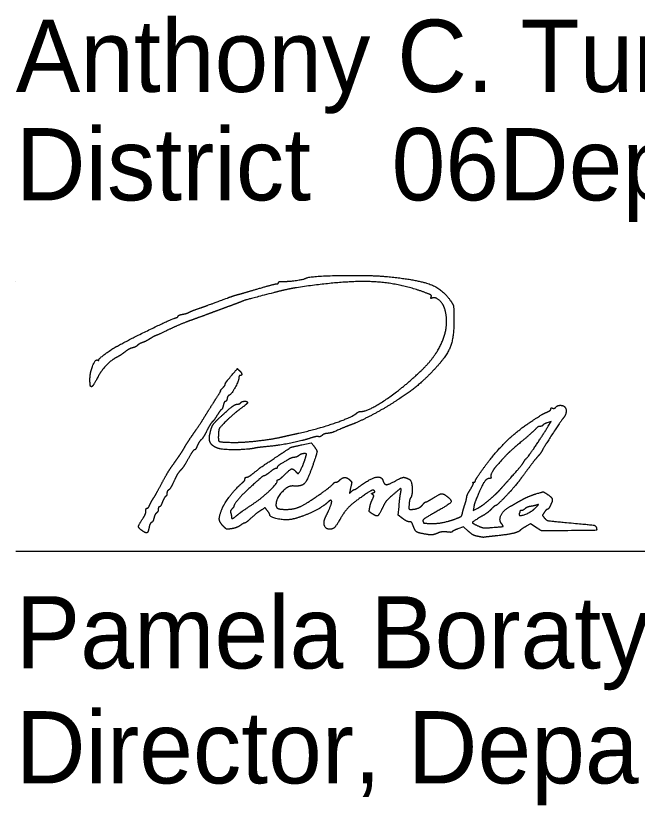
# Model space of a CAD drawing. Extents: x 0 to 34, y 0 to 22.
# Drawn here: x 24.528 to 25.732, y 7.305 to 8.834 of the extents above; entities that cross this region are included whole.
import ezdxf

# ---------------------------------------------------------------- set-up
doc = ezdxf.new("R2010")
doc.units = 0
doc.layers.add('GM_X_Minor_Lake', color=7, linetype='Continuous')
doc.layers.add('GM_X_Minor_Lake_Text', color=7, linetype='Continuous')

msp = doc.modelspace()

# ---------------------------------------------------------------- linework, layer by layer
at = {"layer": 'GM_X_Minor_Lake'}
for points in [[(25.5597, 8.039), (25.5651, 8.0479), (25.5577, 8.0453)], [(25.0824, 8.0028), (25.1004, 8.0068), (25.1051, 8.0007)], [(25.2773, 7.86), (25.269, 7.8663), (25.2704, 7.8834)], [(25.4153, 7.882), (25.4143, 7.8755), (25.4229, 7.8799)], [(25.5361, 7.8426), (25.5255, 7.8494), (25.5171, 7.8449)], [(25.4043, 7.8356), (25.3951, 7.8439), (25.3845, 7.8398)]]:
    msp.add_lwpolyline(points, dxfattribs=at)
for points in [[(25.0368, 8.3169), (25.0368, 8.3183), (25.0408, 8.3193), (25.0458, 8.3192)], [(25.0458, 8.3192), (25.0554, 8.3189), (25.0864, 8.3232), (25.0898, 8.3254)], [(25.3205, 8.2977), (25.2699, 8.3167), (25.1619, 8.3207), (25.0716, 8.3069)], [(25.0898, 8.3254), (25.0966, 8.3295), (25.2136, 8.3318), (25.248, 8.3285)], [(25.248, 8.3285), (25.3072, 8.3226), (25.3548, 8.3043), (25.3706, 8.2813)], [(24.9612, 8.2946), (24.9665, 8.296), (24.9839, 8.301), (25, 8.3058)], [(25, 8.3058), (25.0161, 8.3105), (25.031, 8.3144), (25.033, 8.3144)], [(25.0716, 8.3069), (25.0623, 8.3055), (25.0424, 8.3011), (25.0272, 8.2972)], [(25.033, 8.3144), (25.0351, 8.3144), (25.0368, 8.3156), (25.0368, 8.3169)], [(24.9372, 8.2868), (24.9451, 8.2897), (24.9559, 8.2933), (24.9612, 8.2946)], [(25.0272, 8.2972), (24.9762, 8.284), (24.9719, 8.2828), (24.9612, 8.2784)], [(25.3328, 8.2891), (25.3338, 8.2916), (25.3303, 8.294), (25.3205, 8.2977)], [(25.3352, 8.287), (25.3326, 8.286), (25.3319, 8.2866), (25.3328, 8.2891)], [(24.8808, 8.2662), (24.8955, 8.2713), (24.9019, 8.2737), (24.9372, 8.2868)], [(24.9612, 8.2784), (24.9585, 8.2774), (24.9483, 8.2735), (24.9384, 8.27)], [(25.3586, 8.2671), (25.3553, 8.2769), (25.3409, 8.2892), (25.3352, 8.287)], [(25.3706, 8.2813), (25.3755, 8.274), (25.3764, 8.2697), (25.3768, 8.2518)], [(24.8514, 8.2556), (24.8563, 8.2565), (24.8615, 8.2581), (24.8628, 8.259)], [(24.8628, 8.259), (24.8641, 8.26), (24.8722, 8.2632), (24.8808, 8.2662)], [(24.9048, 8.2575), (24.8962, 8.2543), (24.88, 8.2484), (24.8688, 8.2444)], [(24.9384, 8.27), (24.9285, 8.2664), (24.9134, 8.2608), (24.9048, 8.2575)], [(25.3131, 8.1459), (25.344, 8.1753), (25.3679, 8.2389), (25.3586, 8.2671)], [(24.7248, 8.194), (24.755, 8.2103), (24.8286, 8.2459), (24.837, 8.2484)], [(24.8688, 8.2444), (24.8576, 8.2404), (24.8372, 8.2319), (24.8236, 8.2254)], [(24.837, 8.2484), (24.84, 8.2492), (24.8424, 8.2508), (24.8424, 8.2519)], [(24.8424, 8.2519), (24.8424, 8.253), (24.8464, 8.2547), (24.8514, 8.2556)], [(25.3768, 8.2518), (25.3775, 8.2111), (25.3614, 8.1714), (25.332, 8.1415)], [(24.7977, 8.2136), (24.7971, 8.2136), (24.7927, 8.2111), (24.7877, 8.208)], [(24.8236, 8.2254), (24.8099, 8.2189), (24.7983, 8.2136), (24.7977, 8.2136)], [(24.7729, 8.2005), (24.7697, 8.1994), (24.7655, 8.1971), (24.7637, 8.1953)], [(24.7877, 8.208), (24.7828, 8.2049), (24.7761, 8.2015), (24.7729, 8.2005)], [(24.6888, 8.1674), (24.6888, 8.1696), (24.7142, 8.1883), (24.7248, 8.194)], [(24.7392, 8.1824), (24.7346, 8.1788), (24.7274, 8.1742), (24.7233, 8.1721)], [(24.754, 8.1905), (24.7505, 8.1896), (24.7438, 8.186), (24.7392, 8.1824)], [(24.7637, 8.1953), (24.7619, 8.1935), (24.7576, 8.1913), (24.754, 8.1905)], [(24.6716, 8.1295), (24.6717, 8.1427), (24.6823, 8.1693), (24.6865, 8.1668)], [(24.6865, 8.1668), (24.6877, 8.166), (24.6888, 8.1663), (24.6888, 8.1674)], [(24.7233, 8.1721), (24.7129, 8.1667), (24.693, 8.1459), (24.6868, 8.1338)], [(24.939, 8.1285), (24.9575, 8.1506), (24.9568, 8.15), (24.9609, 8.1467)], [(24.9624, 8.1368), (24.9611, 8.1368), (24.96, 8.1345), (24.96, 8.1317)], [(24.9609, 8.1467), (24.9652, 8.1431), (24.9661, 8.1368), (24.9624, 8.1368)], [(25.1964, 8.0672), (25.2105, 8.0672), (25.2786, 8.1131), (25.3131, 8.1459)], [(25.332, 8.1415), (25.3134, 8.1226), (25.281, 8.0977), (25.2505, 8.0788)], [(24.673, 8.1158), (24.6722, 8.1166), (24.6716, 8.1228), (24.6716, 8.1295)], [(24.6868, 8.1338), (24.6801, 8.1209), (24.6748, 8.114), (24.673, 8.1158)], [(24.9288, 8.1128), (24.9314, 8.1155), (24.9336, 8.1186), (24.9336, 8.1198)], [(24.9336, 8.1198), (24.9336, 8.121), (24.936, 8.1249), (24.939, 8.1285)], [(24.96, 8.1317), (24.96, 8.1262), (24.9441, 8.0984), (24.9409, 8.0984)], [(24.916, 8.0924), (24.9216, 8.101), (24.9256, 8.108), (24.925, 8.108)], [(24.925, 8.108), (24.9245, 8.108), (24.9261, 8.1102), (24.9288, 8.1128)], [(24.894, 8.0574), (24.9006, 8.068), (24.9105, 8.0838), (24.916, 8.0924)], [(24.9374, 8.0924), (24.9366, 8.0891), (24.9349, 8.0864), (24.9337, 8.0864)], [(24.9409, 8.0984), (24.9398, 8.0984), (24.9382, 8.0957), (24.9374, 8.0924)], [(24.9252, 8.0575), (24.9409, 8.0721), (24.9536, 8.0816), (24.9576, 8.0816)], [(24.93, 8.0793), (24.9291, 8.0753), (24.9274, 8.0714), (24.9261, 8.0707)], [(24.9337, 8.0864), (24.9325, 8.0864), (24.9309, 8.0832), (24.93, 8.0793)], [(24.9576, 8.0816), (24.9601, 8.0816), (24.9628, 8.0827), (24.9636, 8.084)], [(24.9768, 8.0844), (24.9768, 8.0833), (24.97, 8.0774), (24.9618, 8.0713)], [(24.9636, 8.084), (24.9654, 8.0869), (24.9768, 8.0873), (24.9768, 8.0844)], [(25.2505, 8.0788), (25.2313, 8.067), (25.1901, 8.046), (25.176, 8.0409)], [(25.5648, 8.0722), (25.5648, 8.0737), (25.5663, 8.0744), (25.5682, 8.0736)], [(25.5682, 8.0736), (25.5701, 8.0729), (25.5729, 8.0739), (25.5745, 8.0758)], [(25.5745, 8.0758), (25.5761, 8.0777), (25.5798, 8.0792), (25.5827, 8.0792)], [(25.5827, 8.0792), (25.5921, 8.0792), (25.5959, 8.0632), (25.5885, 8.0542)], [(24.9176, 8.0592), (24.9142, 8.0537), (24.9101, 8.0481), (24.9084, 8.0468)], [(24.9261, 8.0707), (24.9248, 8.0699), (24.921, 8.0647), (24.9176, 8.0592)], [(24.9618, 8.0713), (24.9535, 8.0652), (24.941, 8.0543), (24.934, 8.0471)], [(25.0764, 8.0253), (25.1133, 8.0335), (25.1796, 8.0564), (25.1882, 8.0639)], [(25.1882, 8.0639), (25.1903, 8.0657), (25.1939, 8.0672), (25.1964, 8.0672)], [(25.528, 8.0488), (25.5469, 8.0611), (25.5488, 8.0622), (25.557, 8.0659)], [(25.557, 8.0659), (25.5613, 8.0678), (25.5648, 8.0706), (25.5648, 8.0722)], [(24.8722, 8.0244), (24.8776, 8.0319), (24.8874, 8.0467), (24.894, 8.0574)], [(24.9084, 8.0468), (24.9068, 8.0455), (24.9021, 8.0378), (24.8981, 8.0299)], [(24.9038, 8.0228), (24.9066, 8.0359), (24.9127, 8.0459), (24.9252, 8.0575)], [(24.934, 8.0471), (24.9233, 8.0362), (24.9211, 8.0325), (24.9206, 8.0243)], [(25.4334, 7.9563), (25.4556, 7.9871), (25.5007, 8.0312), (25.528, 8.0488)], [(25.5885, 8.0542), (25.5843, 8.0492), (25.5515, 7.9987), (25.5483, 7.9926)], [(25.5577, 8.0453), (25.5537, 8.0439), (25.5498, 8.0418), (25.549, 8.0406)], [(24.8981, 8.0299), (24.8941, 8.0219), (24.889, 8.0139), (24.8868, 8.0121)], [(25.1603, 8.0347), (25.1433, 8.0272), (25.1384, 8.0256), (25.1318, 8.0248)], [(25.176, 8.0409), (25.1714, 8.0392), (25.1643, 8.0364), (25.1603, 8.0347)], [(25.5349, 8.033), (25.5322, 8.0301), (25.5197, 8.019), (25.5072, 8.0084)], [(25.5169, 7.976), (25.5197, 7.978), (25.5479, 8.0195), (25.5597, 8.039)], [(25.5437, 8.0384), (25.5415, 8.0384), (25.5375, 8.036), (25.5349, 8.033)], [(25.549, 8.0406), (25.5483, 8.0394), (25.5459, 8.0384), (25.5437, 8.0384)], [(24.8555, 7.9988), (24.8593, 8.0054), (24.8669, 8.0169), (24.8722, 8.0244)], [(24.9192, 7.996), (24.9087, 7.9999), (24.9016, 8.0123), (24.9038, 8.0228)], [(24.9206, 8.0243), (24.9197, 8.0108), (24.9238, 8.008), (24.9444, 8.0074)], [(24.9444, 8.0074), (24.9636, 8.0069), (25.0215, 8.013), (25.0428, 8.0178)], [(25.0962, 8.0148), (25.0797, 8.0095), (25.0346, 8.001), (25.0108, 7.9988)], [(25.0428, 8.0178), (25.0507, 8.0196), (25.0658, 8.023), (25.0764, 8.0253)], [(25.1142, 8.0185), (25.1125, 8.0191), (25.1044, 8.0175), (25.0962, 8.0148)], [(25.121, 8.0207), (25.1189, 8.0189), (25.1158, 8.0179), (25.1142, 8.0185)], [(25.1318, 8.0248), (25.1279, 8.0244), (25.123, 8.0225), (25.121, 8.0207)], [(24.8425, 7.9782), (24.8458, 7.9829), (24.8517, 7.9922), (24.8555, 7.9988)], [(24.8796, 8.0008), (24.8777, 7.9964), (24.8752, 7.9928), (24.8739, 7.9928)], [(24.8868, 8.0121), (24.8847, 8.0103), (24.8814, 8.0052), (24.8796, 8.0008)], [(25.0108, 7.9988), (25.0025, 7.998), (24.9933, 7.9968), (24.9904, 7.9961)], [(25.0284, 7.9764), (25.06, 7.9974), (25.0614, 7.9981), (25.0824, 8.0028)], [(25.1051, 8.0007), (25.1117, 7.9919), (25.1115, 7.987), (25.1038, 7.9645)], [(25.5072, 8.0084), (25.4876, 7.9919), (25.4759, 7.9805), (25.4592, 7.9617)], [(24.8739, 7.9928), (24.8726, 7.9928), (24.8672, 7.9849), (24.8618, 7.9753)], [(24.9904, 7.9961), (24.9767, 7.9931), (24.9272, 7.993), (24.9192, 7.996)], [(25.0765, 7.982), (25.074, 7.98), (25.07, 7.9784), (25.0678, 7.9784)], [(25.0864, 7.9856), (25.0835, 7.9855), (25.0791, 7.9839), (25.0765, 7.982)], [(25.0897, 7.979), (25.0914, 7.9848), (25.091, 7.9856), (25.0864, 7.9856)], [(25.5483, 7.9926), (25.5466, 7.9891), (25.5427, 7.9836), (25.5397, 7.9804)], [(24.8289, 7.959), (24.833, 7.9648), (24.8391, 7.9734), (24.8425, 7.9782)], [(24.8618, 7.9753), (24.8565, 7.9656), (24.8498, 7.9556), (24.847, 7.9531)], [(24.9892, 7.9484), (25.0029, 7.9595), (25.0009, 7.9581), (25.0284, 7.9764)], [(25.0581, 7.9753), (25.0436, 7.9674), (25.0344, 7.961), (25.0344, 7.959)], [(25.0678, 7.9784), (25.0656, 7.9784), (25.0612, 7.977), (25.0581, 7.9753)], [(25.075, 7.9472), (25.0768, 7.9472), (25.0866, 7.9684), (25.0897, 7.979)], [(25.4817, 7.9331), (25.497, 7.9502), (25.5106, 7.9665), (25.513, 7.9709)], [(25.513, 7.9709), (25.5142, 7.9731), (25.5159, 7.9754), (25.5169, 7.976)], [(25.5397, 7.9804), (25.5367, 7.9772), (25.5278, 7.9659), (25.5199, 7.9552)], [(24.81, 7.9268), (24.8163, 7.9387), (24.8248, 7.9532), (24.8289, 7.959)], [(24.847, 7.9531), (24.8441, 7.9505), (24.8386, 7.9414), (24.8347, 7.9328)], [(25.0317, 7.9568), (25.0303, 7.9568), (25.025, 7.9536), (25.02, 7.9496)], [(25.0344, 7.959), (25.0344, 7.9578), (25.0332, 7.9568), (25.0317, 7.9568)], [(25.0488, 7.9448), (25.0589, 7.955), (25.0654, 7.9568), (25.0704, 7.9508)], [(25.1038, 7.9645), (25.0935, 7.9346), (25.0815, 7.9215), (25.0656, 7.9229)], [(25.4184, 7.933), (25.4184, 7.9344), (25.4251, 7.9449), (25.4334, 7.9563)], [(25.4592, 7.9617), (25.4533, 7.955), (25.4471, 7.9422), (25.4485, 7.9398)], [(25.5199, 7.9552), (25.512, 7.9446), (25.5043, 7.9344), (25.5029, 7.9325)], [(24.9666, 7.9288), (24.9695, 7.9312), (24.972, 7.9347), (24.972, 7.9366)], [(24.972, 7.9366), (24.972, 7.9385), (24.9735, 7.94), (24.9754, 7.94)], [(25.0088, 7.9424), (25.0069, 7.9424), (24.9985, 7.9351), (24.9732, 7.9119)], [(24.9754, 7.94), (24.9772, 7.94), (24.9834, 7.9438), (24.9892, 7.9484)], [(25.02, 7.9496), (25.015, 7.9457), (25.01, 7.9424), (25.0088, 7.9424)], [(25.0368, 7.9352), (25.0381, 7.9352), (25.0435, 7.9396), (25.0488, 7.9448)], [(25.0704, 7.9508), (25.072, 7.9489), (25.0741, 7.9472), (25.075, 7.9472)], [(25.1555, 7.9343), (25.1605, 7.9393), (25.1705, 7.9393), (25.1754, 7.9344)], [(25.1935, 7.9218), (25.2138, 7.9369), (25.2365, 7.9425), (25.2395, 7.9331)], [(25.2633, 7.9327), (25.2752, 7.9393), (25.2825, 7.9401), (25.2907, 7.9355)], [(25.4462, 7.9376), (25.4399, 7.9376), (25.4304, 7.9225), (25.4183, 7.8932)], [(25.4485, 7.9398), (25.4493, 7.9386), (25.4482, 7.9376), (25.4462, 7.9376)], [(24.7946, 7.8992), (24.7968, 7.9025), (24.8037, 7.915), (24.81, 7.9268)], [(24.8347, 7.9328), (24.8307, 7.9243), (24.826, 7.9164), (24.8242, 7.9153)], [(24.9285, 7.8806), (24.933, 7.891), (24.9562, 7.9205), (24.9666, 7.9288)], [(24.9883, 7.8886), (25.0039, 7.899), (25.0344, 7.9278), (25.0344, 7.9321)], [(25.0656, 7.9229), (25.0552, 7.9238), (25.032, 7.8984), (25.032, 7.8861)], [(25.0344, 7.9321), (25.0344, 7.9338), (25.0355, 7.9352), (25.0368, 7.9352)], [(25.1004, 7.8956), (25.119, 7.9079), (25.1414, 7.9246), (25.1431, 7.9274)], [(25.1431, 7.9274), (25.1442, 7.9291), (25.1465, 7.9304), (25.1483, 7.9304)], [(25.1483, 7.9304), (25.1501, 7.9304), (25.1534, 7.9322), (25.1555, 7.9343)], [(25.1754, 7.9344), (25.1786, 7.9312), (25.1788, 7.9288), (25.1767, 7.9196)], [(25.1841, 7.916), (25.1851, 7.916), (25.1893, 7.9186), (25.1935, 7.9218)], [(25.2395, 7.9331), (25.2419, 7.9255), (25.25, 7.9254), (25.2633, 7.9327)], [(25.2907, 7.9355), (25.2951, 7.933), (25.2967, 7.905), (25.2928, 7.8998)], [(25.4086, 7.9161), (25.4125, 7.9224), (25.415, 7.9282), (25.4142, 7.929)], [(25.4142, 7.929), (25.4134, 7.9298), (25.414, 7.9304), (25.4156, 7.9304)], [(25.4156, 7.9304), (25.4171, 7.9304), (25.4184, 7.9316), (25.4184, 7.933)], [(25.4661, 7.9156), (25.4692, 7.9191), (25.4762, 7.927), (25.4817, 7.9331)], [(25.5029, 7.9325), (25.4896, 7.9161), (25.485, 7.911), (25.4732, 7.8988)], [(24.8208, 7.9089), (24.8208, 7.9064), (24.8197, 7.9036), (24.8183, 7.9028)], [(24.8242, 7.9153), (24.8223, 7.9143), (24.8208, 7.9113), (24.8208, 7.9089)], [(24.9732, 7.9119), (24.9641, 7.9035), (24.9504, 7.8865), (24.9504, 7.8835)], [(25.1767, 7.9196), (25.1744, 7.9094), (25.1745, 7.9089), (25.1783, 7.9123)], [(25.1783, 7.9123), (25.1805, 7.9144), (25.1832, 7.916), (25.1841, 7.916)], [(25.2222, 7.9139), (25.2204, 7.9158), (25.2145, 7.913), (25.202, 7.9045)], [(25.2194, 7.9063), (25.2172, 7.9077), (25.2175, 7.9086), (25.2206, 7.9098)], [(25.2187, 7.8965), (25.2215, 7.9027), (25.2217, 7.9049), (25.2194, 7.9063)], [(25.2206, 7.9098), (25.2236, 7.9109), (25.224, 7.9121), (25.2222, 7.9139)], [(25.2633, 7.9099), (25.2474, 7.8958), (25.2437, 7.8914), (25.2382, 7.8801)], [(25.2734, 7.9082), (25.2752, 7.9177), (25.2726, 7.9181), (25.2633, 7.9099)], [(25.2704, 7.8834), (25.2712, 7.8928), (25.2726, 7.9039), (25.2734, 7.9082)], [(25.336, 7.8992), (25.3489, 7.9075), (25.3565, 7.9083), (25.3642, 7.9022)], [(25.4016, 7.9014), (25.4016, 7.9032), (25.4047, 7.9098), (25.4086, 7.9161)], [(25.446, 7.8968), (25.4539, 7.9036), (25.4629, 7.9121), (25.4661, 7.9156)], [(25.506, 7.8948), (25.5139, 7.8993), (25.5271, 7.905), (25.5353, 7.9075)], [(25.5353, 7.9075), (25.5493, 7.9117), (25.5505, 7.9117), (25.5564, 7.9079)], [(25.5564, 7.9079), (25.566, 7.9016), (25.5684, 7.8942), (25.5638, 7.8852)], [(24.7877, 7.8866), (24.7893, 7.8903), (24.7924, 7.8959), (24.7946, 7.8992)], [(24.812, 7.8918), (24.81, 7.8867), (24.8073, 7.8824), (24.8061, 7.8824)], [(24.8183, 7.9028), (24.8169, 7.9019), (24.8141, 7.897), (24.812, 7.8918)], [(25.0519, 7.8776), (25.065, 7.8776), (25.0841, 7.8847), (25.1004, 7.8956)], [(25.1324, 7.8914), (25.1228, 7.8822), (25.084, 7.8635), (25.0656, 7.859)], [(25.1294, 7.8656), (25.1335, 7.8733), (25.14, 7.8896), (25.14, 7.8923)], [(25.14, 7.8923), (25.14, 7.8954), (25.136, 7.8949), (25.1324, 7.8914)], [(25.202, 7.9045), (25.1823, 7.8911), (25.1651, 7.874), (25.1568, 7.8596)], [(25.2136, 7.8808), (25.2144, 7.885), (25.2166, 7.892), (25.2187, 7.8965)], [(25.2928, 7.8998), (25.2916, 7.8982), (25.2903, 7.8925), (25.2899, 7.8872)], [(25.3168, 7.8872), (25.3187, 7.8898), (25.3212, 7.892), (25.3224, 7.892)], [(25.3224, 7.892), (25.3236, 7.892), (25.3297, 7.8953), (25.336, 7.8992)], [(25.3642, 7.9022), (25.3739, 7.8946), (25.367, 7.8867), (25.3354, 7.8689)], [(25.3981, 7.8872), (25.4, 7.8932), (25.4016, 7.8995), (25.4016, 7.9014)], [(25.4183, 7.8932), (25.4172, 7.8906), (25.4159, 7.8855), (25.4153, 7.882)], [(25.4229, 7.8799), (25.4277, 7.8824), (25.4381, 7.8899), (25.446, 7.8968)], [(25.4732, 7.8988), (25.4657, 7.8911), (25.4586, 7.8848), (25.4576, 7.8848)], [(25.4864, 7.8838), (25.4893, 7.8853), (25.4981, 7.8903), (25.506, 7.8948)], [(24.78, 7.8744), (24.78, 7.8775), (24.7811, 7.88), (24.7824, 7.88)], [(24.7824, 7.88), (24.7838, 7.88), (24.7862, 7.883), (24.7877, 7.8866)], [(24.804, 7.8779), (24.804, 7.8754), (24.8024, 7.8721), (24.8005, 7.8706)], [(24.8061, 7.8824), (24.8049, 7.8824), (24.804, 7.8804), (24.804, 7.8779)], [(24.9302, 7.8448), (24.9225, 7.8524), (24.9219, 7.8653), (24.9285, 7.8806)], [(24.9466, 7.8783), (24.9446, 7.8763), (24.9435, 7.873), (24.9442, 7.8711)], [(24.9504, 7.8835), (24.9504, 7.8827), (24.9487, 7.8804), (24.9466, 7.8783)], [(24.9568, 7.8663), (24.9643, 7.8724), (24.9696, 7.8761), (24.9883, 7.8886)], [(25.0041, 7.8765), (24.9959, 7.8711), (24.9933, 7.8691), (24.9821, 7.859)], [(25.0154, 7.8751), (25.0109, 7.8809), (25.0108, 7.8809), (25.0041, 7.8765)], [(25.0199, 7.8677), (25.0199, 7.8685), (25.0179, 7.8719), (25.0154, 7.8751)], [(25.032, 7.8861), (25.032, 7.881), (25.0398, 7.8776), (25.0519, 7.8776)], [(25.2182, 7.8693), (25.2132, 7.8726), (25.2124, 7.8746), (25.2136, 7.8808)], [(25.2382, 7.8801), (25.2315, 7.8664), (25.2267, 7.8638), (25.2182, 7.8693)], [(25.2899, 7.8872), (25.2894, 7.8796), (25.2901, 7.8776), (25.2932, 7.8776)], [(25.2932, 7.8776), (25.3016, 7.8776), (25.3136, 7.8825), (25.3168, 7.8872)], [(25.3933, 7.8702), (25.394, 7.8736), (25.3961, 7.8813), (25.3981, 7.8872)], [(25.449, 7.8779), (25.4454, 7.874), (25.4373, 7.8679), (25.431, 7.8643)], [(25.4576, 7.8848), (25.4565, 7.8848), (25.4526, 7.8817), (25.449, 7.8779)], [(25.4694, 7.8494), (25.4633, 7.8568), (25.4731, 7.8765), (25.4864, 7.8838)], [(25.5033, 7.8695), (25.5008, 7.863), (25.5263, 7.8719), (25.5348, 7.8805)], [(25.5076, 7.8752), (25.506, 7.8752), (25.5048, 7.8748), (25.5048, 7.8742)], [(25.5144, 7.8788), (25.5122, 7.8769), (25.5091, 7.8752), (25.5076, 7.8752)], [(25.5254, 7.8834), (25.5215, 7.8828), (25.5166, 7.8808), (25.5144, 7.8788)], [(25.5372, 7.8861), (25.5345, 7.8851), (25.5292, 7.8839), (25.5254, 7.8834)], [(25.5348, 7.8805), (25.5403, 7.8861), (25.5408, 7.8875), (25.5372, 7.8861)], [(25.5578, 7.8776), (25.5567, 7.8776), (25.554, 7.875), (25.5519, 7.8718)], [(25.5638, 7.8852), (25.5616, 7.881), (25.5589, 7.8776), (25.5578, 7.8776)], [(24.7725, 7.8364), (24.7655, 7.8413), (24.7659, 7.848), (24.7742, 7.8601)], [(24.7742, 7.8601), (24.7774, 7.8648), (24.78, 7.8712), (24.78, 7.8744)], [(24.7955, 7.8605), (24.7946, 7.8565), (24.7925, 7.8528), (24.7908, 7.8521)], [(24.8005, 7.8706), (24.7986, 7.869), (24.7964, 7.8645), (24.7955, 7.8605)], [(24.9442, 7.8711), (24.945, 7.8692), (24.9456, 7.8661), (24.9456, 7.8642)], [(24.9456, 7.8642), (24.9456, 7.8594), (24.949, 7.86), (24.9568, 7.8663)], [(25.0656, 7.859), (25.0527, 7.8559), (25.0201, 7.8621), (25.0199, 7.8677)], [(25.1361, 7.8392), (25.1277, 7.8392), (25.1237, 7.855), (25.1294, 7.8656)], [(25.1568, 7.8596), (25.1486, 7.8455), (25.1422, 7.8392), (25.1361, 7.8392)], [(25.2903, 7.8536), (25.2877, 7.8536), (25.2819, 7.8565), (25.2773, 7.86)], [(25.3354, 7.8689), (25.3222, 7.8615), (25.316, 7.8567), (25.3168, 7.8545)], [(25.3806, 7.8595), (25.3894, 7.8629), (25.3923, 7.8654), (25.3933, 7.8702)], [(25.431, 7.8643), (25.4131, 7.8539), (25.412, 7.8506), (25.425, 7.845)], [(25.5048, 7.8742), (25.5048, 7.8737), (25.5041, 7.8715), (25.5033, 7.8695)], [(25.5519, 7.8718), (25.5484, 7.8665), (25.5484, 7.8656), (25.5523, 7.8609)], [(25.5523, 7.8609), (25.5559, 7.8564), (25.5609, 7.8553), (25.5948, 7.8522)], [(24.7908, 7.8521), (24.7891, 7.8514), (24.787, 7.8473), (24.7862, 7.8429)], [(24.9464, 7.8402), (24.9377, 7.8389), (24.9355, 7.8395), (24.9302, 7.8448)], [(24.9629, 7.8465), (24.9593, 7.8439), (24.9519, 7.8411), (24.9464, 7.8402)], [(24.9714, 7.8512), (24.9703, 7.8512), (24.9665, 7.8491), (24.9629, 7.8465)], [(24.9821, 7.859), (24.9773, 7.8547), (24.9725, 7.8512), (24.9714, 7.8512)], [(25.2978, 7.8458), (25.296, 7.851), (25.2934, 7.8536), (25.2903, 7.8536)], [(25.3232, 7.8293), (25.3082, 7.8317), (25.3013, 7.8362), (25.2978, 7.8458)], [(25.3168, 7.8545), (25.3181, 7.8511), (25.3188, 7.8509), (25.3308, 7.8502)], [(25.3308, 7.8502), (25.3413, 7.8496), (25.3674, 7.8545), (25.3806, 7.8595)], [(25.425, 7.845), (25.4318, 7.8421), (25.4383, 7.8415), (25.4518, 7.8426)], [(25.4518, 7.8426), (25.4713, 7.8442), (25.4731, 7.8448), (25.4694, 7.8494)], [(25.5171, 7.8449), (25.5125, 7.8425), (25.5072, 7.8389), (25.5054, 7.8371)], [(25.5948, 7.8522), (25.6439, 7.8477), (25.6521, 7.8461), (25.6531, 7.8413)], [(24.7862, 7.8429), (24.7843, 7.8331), (24.7801, 7.8312), (24.7725, 7.8364)], [(25.3443, 7.8312), (25.3373, 7.8284), (25.3318, 7.8279), (25.3232, 7.8293)], [(25.3632, 7.8338), (25.3574, 7.8345), (25.3501, 7.8336), (25.3443, 7.8312)], [(25.3733, 7.8341), (25.3729, 7.8332), (25.3683, 7.8331), (25.3632, 7.8338)], [(25.3845, 7.8398), (25.3787, 7.8376), (25.3737, 7.835), (25.3733, 7.8341)], [(25.4189, 7.8262), (25.4159, 7.8268), (25.4093, 7.8311), (25.4043, 7.8356)], [(25.5054, 7.8371), (25.5017, 7.8334), (25.4802, 7.8285), (25.4568, 7.8261)], [(25.5828, 7.8362), (25.5471, 7.8358), (25.5467, 7.8359), (25.5361, 7.8426)], [(25.6531, 7.8413), (25.6539, 7.8371), (25.6519, 7.837), (25.5828, 7.8362)], [(25.4292, 7.824), (25.4265, 7.8246), (25.4219, 7.8255), (25.4189, 7.8262)], [(25.4376, 7.8238), (25.4356, 7.8234), (25.4318, 7.8235), (25.4292, 7.824)], [(25.4568, 7.8261), (25.4482, 7.8252), (25.4396, 7.8242), (25.4376, 7.8238)]]:
    msp.add_open_spline(points, degree=2, dxfattribs=at)
at = {"layer": 'GM_X_Minor_Lake_Text'}
for p, q in [((24.5279, 8.3191), (24.5279, 8.3191)), ((24.5279, 7.7968), (28.0279, 7.7968))]:
    msp.add_line(p, q, dxfattribs=at)

# ---------------------------------------------------------------- texts
at = {"layer": 'GM_X_Minor_Lake'}
for s, p in [('Anthony C. Turowski, P.E.', (24.5279, 8.6862)), ('District       Deputy Director', (24.5279, 8.4762)), ('              06', (24.5279, 8.4762)), ('Pamela Boratyn', (24.5279, 7.5695)), ('Director, Department of Transportation', (24.5279, 7.3468))]:
    msp.add_text(s, height=0.14, dxfattribs=at).set_placement(p)

doc.saveas('drawing.dxf')
